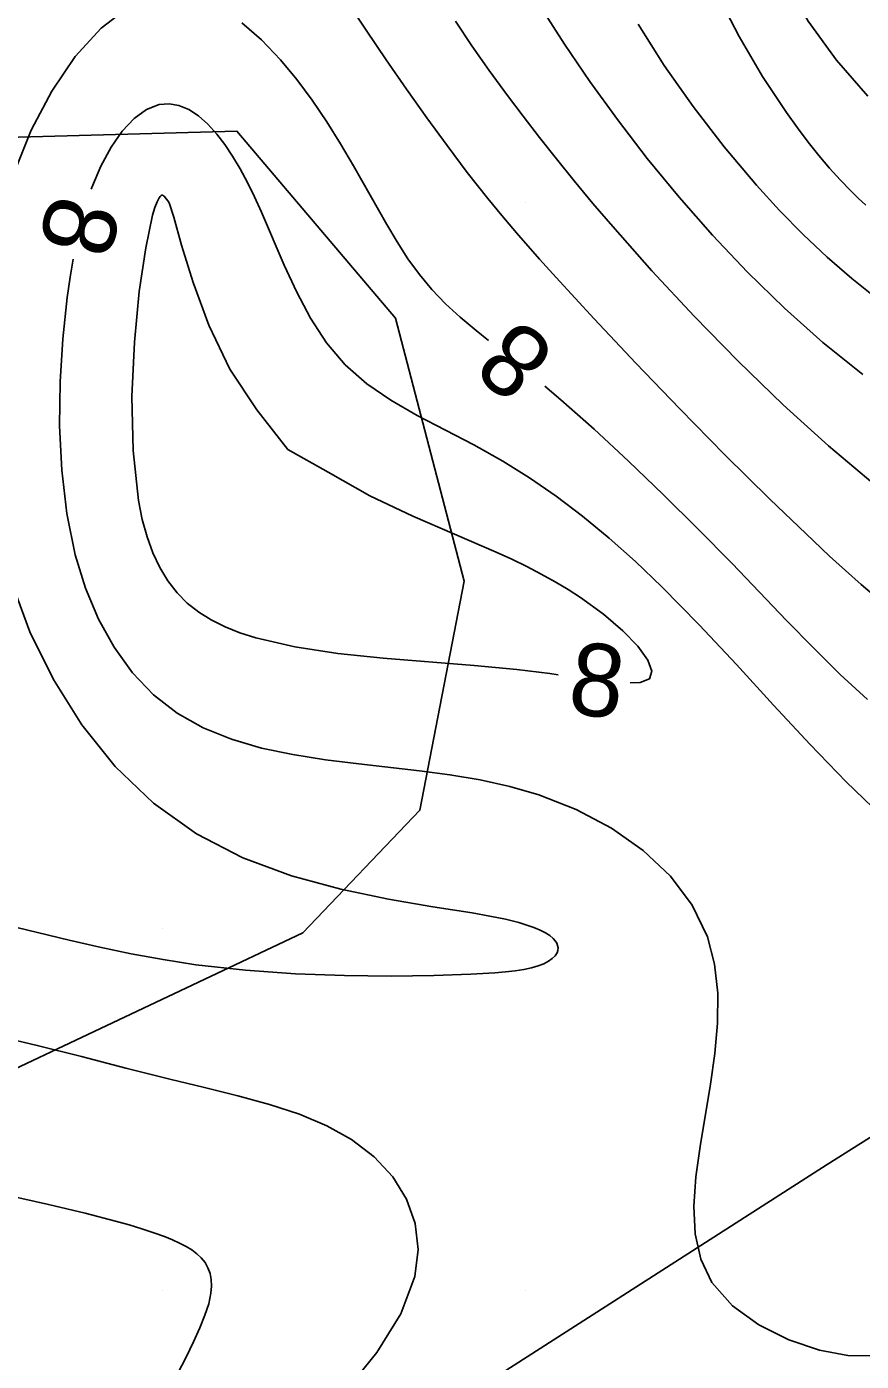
# Model space of a CAD drawing. Extents: x 2602990 to 2605851, y 618069 to 619180.
# Drawn here: x 2603166.25 to 2603189.25, y 618398.06 to 618434.86 of the extents above; entities that cross this region are included whole.
import ezdxf

# ---------------------------------------------------------------- set-up
doc = ezdxf.new("R2010")
doc.units = 0
for name, color, linetype in [('DTM Contours Major', 7, 'Continuous'), ('DTM Contours Major Text', 7, 'Continuous'), ('DTM Contours Minor', 7, 'Continuous'), ('DTM Contours Minor Text', 7, 'Continuous'), ('Exist DTM QL2 LIDAR Elevation Point', 7, 'Continuous'), ('Exist Roads EOP', 7, 'Continuous'), ('PH Exist DTM Obscure Area', 7, 'Continuous')]:
    doc.layers.add(name, color=color, linetype=linetype)

msp = doc.modelspace()

# ---------------------------------------------------------------- linework, layer by layer
at = {"layer": 'DTM Contours Major'}
for points in [[(2603189.811, 618413.102), (2603188.839, 618414.034), (2603187.845, 618415.064), (2603186.834, 618416.154), (2603185.812, 618417.268), (2603184.784, 618418.367), (2603183.756, 618419.414), (2603183.027, 618420.109), (2603182.298, 618420.759), (2603181.57, 618421.361), (2603180.84, 618421.916), (2603180.107, 618422.422), (2603179.371, 618422.88), (2603178.57, 618423.325), (2603177.012, 618424.138), (2603176.287, 618424.556), (2603175.619, 618425.014), (2603175.024, 618425.537), (2603174.512, 618426.143), (2603174.072, 618426.817), (2603173.689, 618427.537), (2603173.347, 618428.279), (2603172.717, 618429.744), (2603172.525, 618430.163), (2603172.329, 618430.562), (2603172.129, 618430.938), (2603171.922, 618431.289), (2603171.709, 618431.609), (2603171.489, 618431.897), (2603171.237, 618432.172), (2603170.978, 618432.398), (2603170.712, 618432.57), (2603170.443, 618432.683), (2603170.171, 618432.732), (2603169.898, 618432.711), (2603169.548, 618432.577), (2603169.206, 618432.33), (2603168.878, 618431.98), (2603168.571, 618431.538), (2603168.289, 618431.015), (2603168.04, 618430.422), (2603168.025, 618430.378)], [(2603167.525, 618428.444), (2603167.443, 618427.954), (2603167.363, 618427.388), (2603167.241, 618426.253), (2603167.168, 618425.065), (2603167.154, 618423.849), (2603167.212, 618422.632), (2603167.351, 618421.438), (2603167.585, 618420.296), (2603167.866, 618419.379), (2603168.222, 618418.526), (2603168.654, 618417.746), (2603169.161, 618417.047), (2603169.743, 618416.438), (2603170.398, 618415.927), (2603171.114, 618415.525), (2603171.891, 618415.211), (2603172.718, 618414.97), (2603173.587, 618414.787), (2603174.486, 618414.646), (2603175.406, 618414.531), (2603177.078, 618414.342), (2603177.914, 618414.231), (2603178.743, 618414.092), (2603179.56, 618413.913), (2603180.36, 618413.682), (2603181.397, 618413.274), (2603182.366, 618412.758), (2603183.239, 618412.142), (2603183.99, 618411.432), (2603184.59, 618410.638), (2603185.011, 618409.767), (2603185.21, 618409.006), (2603185.295, 618408.21), (2603185.289, 618407.386), (2603185.215, 618406.545), (2603185.095, 618405.697), (2603184.807, 618403.986), (2603184.691, 618403.146), (2603184.636, 618402.339), (2603184.672, 618401.578), (2603184.828, 618400.872), (2603185.136, 618400.234), (2603185.7, 618399.592), (2603186.431, 618399.062), (2603187.256, 618398.651), (2603188.099, 618398.368), (2603188.885, 618398.218), (2603189.541, 618398.211)], [(2603165.332, 618407.05), (2603166.536, 618406.768), (2603167.758, 618406.46), (2603168.983, 618406.146), (2603170.195, 618405.84), (2603171.144, 618405.61), (2603172.063, 618405.382), (2603172.94, 618405.14), (2603173.763, 618404.87), (2603174.521, 618404.555), (2603175.2, 618404.18), (2603175.826, 618403.702), (2603176.335, 618403.149), (2603176.715, 618402.532), (2603176.953, 618401.861), (2603177.034, 618401.146), (2603176.946, 618400.4), (2603176.558, 618399.373), (2603175.895, 618398.306), (2603175.007, 618397.199)]]:
    msp.add_lwpolyline(points, dxfattribs=at)
at = {"layer": 'DTM Contours Minor'}
for points in [[(2603189.754, 618449.488), (2603188.811, 618447.952), (2603187.947, 618446.378), (2603187.204, 618444.785), (2603186.626, 618443.191), (2603186.255, 618441.613), (2603186.133, 618440.07), (2603186.262, 618438.716), (2603186.601, 618437.416), (2603187.118, 618436.178), (2603187.783, 618435.013), (2603188.566, 618433.931), (2603189.436, 618432.941)], [(2603185.281, 618435.766), (2603185.881, 618434.586), (2603186.531, 618433.487), (2603187.192, 618432.492), (2603187.492, 618432.071), (2603187.788, 618431.676), (2603188.081, 618431.307), (2603188.373, 618430.961), (2603188.665, 618430.637), (2603188.959, 618430.333), (2603189.166, 618430.133), (2603189.377, 618429.941)], [(2603165.913, 618430.857), (2603166.373, 618432.009), (2603166.937, 618433.084), (2603167.585, 618434.037), (2603168.295, 618434.82), (2603169.048, 618435.389)], [(2603175.055, 618435.586), (2603175.603, 618434.761), (2603176.156, 618433.943), (2603176.714, 618433.137), (2603177.274, 618432.348), (2603177.834, 618431.581), (2603178.392, 618430.842), (2603178.957, 618430.122), (2603179.343, 618429.649), (2603179.744, 618429.176), (2603180.384, 618428.448), (2603180.844, 618427.939), (2603181.89, 618426.801), (2603183.037, 618425.581), (2603184.248, 618424.318), (2603185.491, 618423.054), (2603186.729, 618421.827), (2603187.93, 618420.679), (2603188.378, 618420.263), (2603188.817, 618419.865), (2603189.25, 618419.482), (2603189.679, 618419.113)], [(2603180.446, 618435.354), (2603181.075, 618434.376), (2603181.772, 618433.351), (2603182.533, 618432.295), (2603183.353, 618431.226), (2603184.227, 618430.158), (2603185.148, 618429.109), (2603186.117, 618428.086), (2603187.131, 618427.098), (2603188.19, 618426.155), (2603189.291, 618425.264)], [(2603172.173, 618434.966), (2603172.722, 618434.492), (2603173.245, 618433.944), (2603173.693, 618433.402), (2603174.117, 618432.829), (2603174.518, 618432.233), (2603174.897, 618431.627), (2603175.257, 618431.018), (2603176.172, 618429.403), (2603176.459, 618428.922), (2603176.756, 618428.461), (2603177.073, 618428.023), (2603177.415, 618427.609), (2603177.79, 618427.221), (2603178.196, 618426.848), (2603178.632, 618426.481), (2603178.98, 618426.203)], [(2603178.063, 618435.009), (2603178.514, 618434.329), (2603178.993, 618433.649), (2603179.496, 618432.965), (2603179.93, 618432.389), (2603180.38, 618431.806), (2603180.849, 618431.213), (2603181.34, 618430.607), (2603181.856, 618429.986), (2603182.4, 618429.349), (2603183.481, 618428.129), (2603184.641, 618426.879), (2603185.857, 618425.634), (2603187.101, 618424.428), (2603188.349, 618423.297), (2603189.574, 618422.276)], [(2603183.099, 618434.93), (2603183.82, 618433.791), (2603184.616, 618432.654), (2603185.469, 618431.544), (2603186.361, 618430.485), (2603186.999, 618429.788), (2603187.648, 618429.128), (2603188.311, 618428.505), (2603188.989, 618427.917), (2603189.684, 618427.364)], [(2603170.099, 618430.099), (2603170.036, 618430.181), (2603170.018, 618430.198), (2603170, 618430.21), (2603169.975, 618430.213), (2603169.95, 618430.203), (2603169.923, 618430.179), (2603169.896, 618430.143), (2603169.84, 618430.032), (2603169.78, 618429.87), (2603169.719, 618429.66), (2603169.527, 618428.762), (2603169.35, 618427.559), (2603169.216, 618426.157), (2603169.149, 618424.658), (2603169.177, 618423.169), (2603169.326, 618421.793), (2603169.431, 618421.273), (2603169.563, 618420.791), (2603169.724, 618420.348), (2603169.914, 618419.943), (2603170.136, 618419.578), (2603170.39, 618419.252), (2603170.673, 618418.968), (2603170.989, 618418.719), (2603171.336, 618418.502), (2603171.715, 618418.313), (2603172.125, 618418.149), (2603172.565, 618418.007), (2603173.641, 618417.757), (2603174.823, 618417.578), (2603176.068, 618417.447), (2603178.577, 618417.248), (2603179.755, 618417.137), (2603180.662, 618417.024), (2603180.895, 618416.991)], [(2603182.88, 618416.764), (2603183.161, 618416.773), (2603183.41, 618416.875), (2603183.476, 618417.088), (2603183.364, 618417.395), (2603183.093, 618417.775), (2603182.681, 618418.204), (2603182.147, 618418.66), (2603181.512, 618419.119), (2603181.171, 618419.338), (2603180.811, 618419.553), (2603180.432, 618419.764), (2603180.035, 618419.971), (2603179.621, 618420.174), (2603179.19, 618420.374), (2603176.886, 618421.366), (2603175.702, 618421.926), (2603174.561, 618422.577), (2603173.449, 618423.201), (2603172.593, 618424.297), (2603171.849, 618425.418), (2603171.269, 618426.624), (2603170.832, 618427.801), (2603170.517, 618428.833), (2603170.304, 618429.605), (2603170.171, 618430), (2603170.135, 618430.053), (2603170.099, 618430.099)], [(2603180.533, 618424.943), (2603180.972, 618424.572), (2603181.888, 618423.757), (2603182.831, 618422.881), (2603183.789, 618421.96), (2603184.745, 618421.012), (2603185.688, 618420.053), (2603187.192, 618418.489), (2603187.931, 618417.731), (2603188.672, 618417.001), (2603189.42, 618416.304)], [(2603164.791, 618410.304), (2603167.421, 618409.672), (2603168.266, 618409.479), (2603169.128, 618409.298), (2603170.008, 618409.135), (2603170.909, 618408.996), (2603172.277, 618408.843), (2603173.657, 618408.745), (2603175.009, 618408.695), (2603176.292, 618408.682), (2603177.467, 618408.699), (2603178.493, 618408.735), (2603179.155, 618408.773), (2603179.446, 618408.798), (2603179.709, 618408.828), (2603179.947, 618408.864), (2603180.157, 618408.909), (2603180.341, 618408.962), (2603180.498, 618409.023), (2603180.63, 618409.091), (2603180.735, 618409.165), (2603180.813, 618409.243), (2603180.865, 618409.327), (2603180.886, 618409.391), (2603180.892, 618409.456), (2603180.882, 618409.522), (2603180.856, 618409.588), (2603180.814, 618409.654), (2603180.756, 618409.719), (2603180.662, 618409.798), (2603180.543, 618409.874), (2603180.399, 618409.948), (2603180.23, 618410.02), (2603180.035, 618410.089), (2603179.815, 618410.155), (2603179.44, 618410.247), (2603179.01, 618410.335), (2603178.526, 618410.421), (2603177.446, 618410.594), (2603176.221, 618410.802), (2603174.902, 618411.076), (2603173.545, 618411.446), (2603172.201, 618411.944), (2603170.925, 618412.6), (2603169.743, 618413.45), (2603168.689, 618414.464), (2603167.768, 618415.61), (2603166.982, 618416.856), (2603166.337, 618418.17), (2603165.835, 618419.52)], [(2603165.741, 618402.629), (2603166.845, 618402.387), (2603167.859, 618402.143), (2603168.694, 618401.926), (2603169.073, 618401.819), (2603169.425, 618401.713), (2603169.75, 618401.606), (2603170.047, 618401.499), (2603170.264, 618401.411), (2603170.462, 618401.322), (2603170.641, 618401.228), (2603170.8, 618401.13), (2603170.94, 618401.025), (2603171.059, 618400.912), (2603171.164, 618400.781), (2603171.244, 618400.639), (2603171.301, 618400.484), (2603171.333, 618400.316), (2603171.34, 618400.133), (2603171.323, 618399.935), (2603171.263, 618399.647), (2603171.161, 618399.329), (2603171.022, 618398.979), (2603170.847, 618398.595), (2603170.64, 618398.176), (2603170.403, 618397.719)]]:
    msp.add_lwpolyline(points, dxfattribs=at)
at = {"layer": 'Exist DTM QL2 LIDAR Elevation Point'}
for p, q in [((2603170, 618430), (2603170, 618430)), ((2603180, 618430), (2603180, 618430)), ((2603170, 618420), (2603170, 618420)), ((2603180, 618420), (2603180, 618420)), ((2603170, 618410), (2603170, 618410)), ((2603180, 618410), (2603180, 618410)), ((2603170, 618400), (2603170, 618400)), ((2603180, 618400), (2603180, 618400))]:
    msp.add_line(p, q, dxfattribs=at)
at = {"layer": 'Exist Roads EOP'}
msp.add_spline([(2604034.633, 618668.486), (2603984.89, 618650.123), (2603936.767, 618631.654), (2603888.195, 618613.335), (2603837.766, 618594.258), (2603782.918, 618573.705), (2603731.939, 618554.39), (2603671.126, 618532.171), (2603621.822, 618514.106), (2603561.545, 618491.877), (2603506.421, 618471.293), (2603452.163, 618451.33), (2603398.364, 618431.316), (2603341.431, 618410.355), (2603281.65, 618388.199), (2603223.033, 618366.475), (2603185.717, 618352.612)], degree=3, dxfattribs=at)
at = {"layer": 'PH Exist DTM Obscure Area'}
for points in [[(2603158.394, 618395.561), (2603158.433, 618403.627), (2603165.226, 618405.794), (2603173.861, 618409.877), (2603177.085, 618413.253), (2603178.307, 618419.571), (2603176.417, 618426.82), (2603172.042, 618431.974), (2603163.334, 618431.741), (2603155.337, 618426.922), (2603153.556, 618418.773), (2603152.384, 618403.748), (2603150.149, 618396.334)], [(2603195.666, 618408.122), (2603188.311, 618403.483), (2603176.819, 618396.115)]]:
    msp.add_lwpolyline(points, dxfattribs=at)

# ---------------------------------------------------------------- texts
at = {"layer": 'DTM Contours Major Text'}
msp.add_text('8', height=2, rotation=255.5148, dxfattribs=at).set_placement((2603166.93, 618430.305))
at = {"layer": 'DTM Contours Minor Text'}
for rotation, p in [(140.9399, (2603180.899, 618425.944)), (353.4652, (2603181.122, 618415.933))]:
    msp.add_text('8', height=2, rotation=rotation, dxfattribs=at).set_placement(p)

doc.saveas('drawing.dxf')
